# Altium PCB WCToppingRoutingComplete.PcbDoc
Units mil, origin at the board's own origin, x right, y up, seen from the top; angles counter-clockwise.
Board outline 4005 x 4000 mil, 4 copper layers (Top Layer, GND, 5V, Bottom Layer), stack 30.634 mil thick; 56 components, 71 nets, 273 pads, 45 vias.
Unrouted connection lines stored in the file: 67.
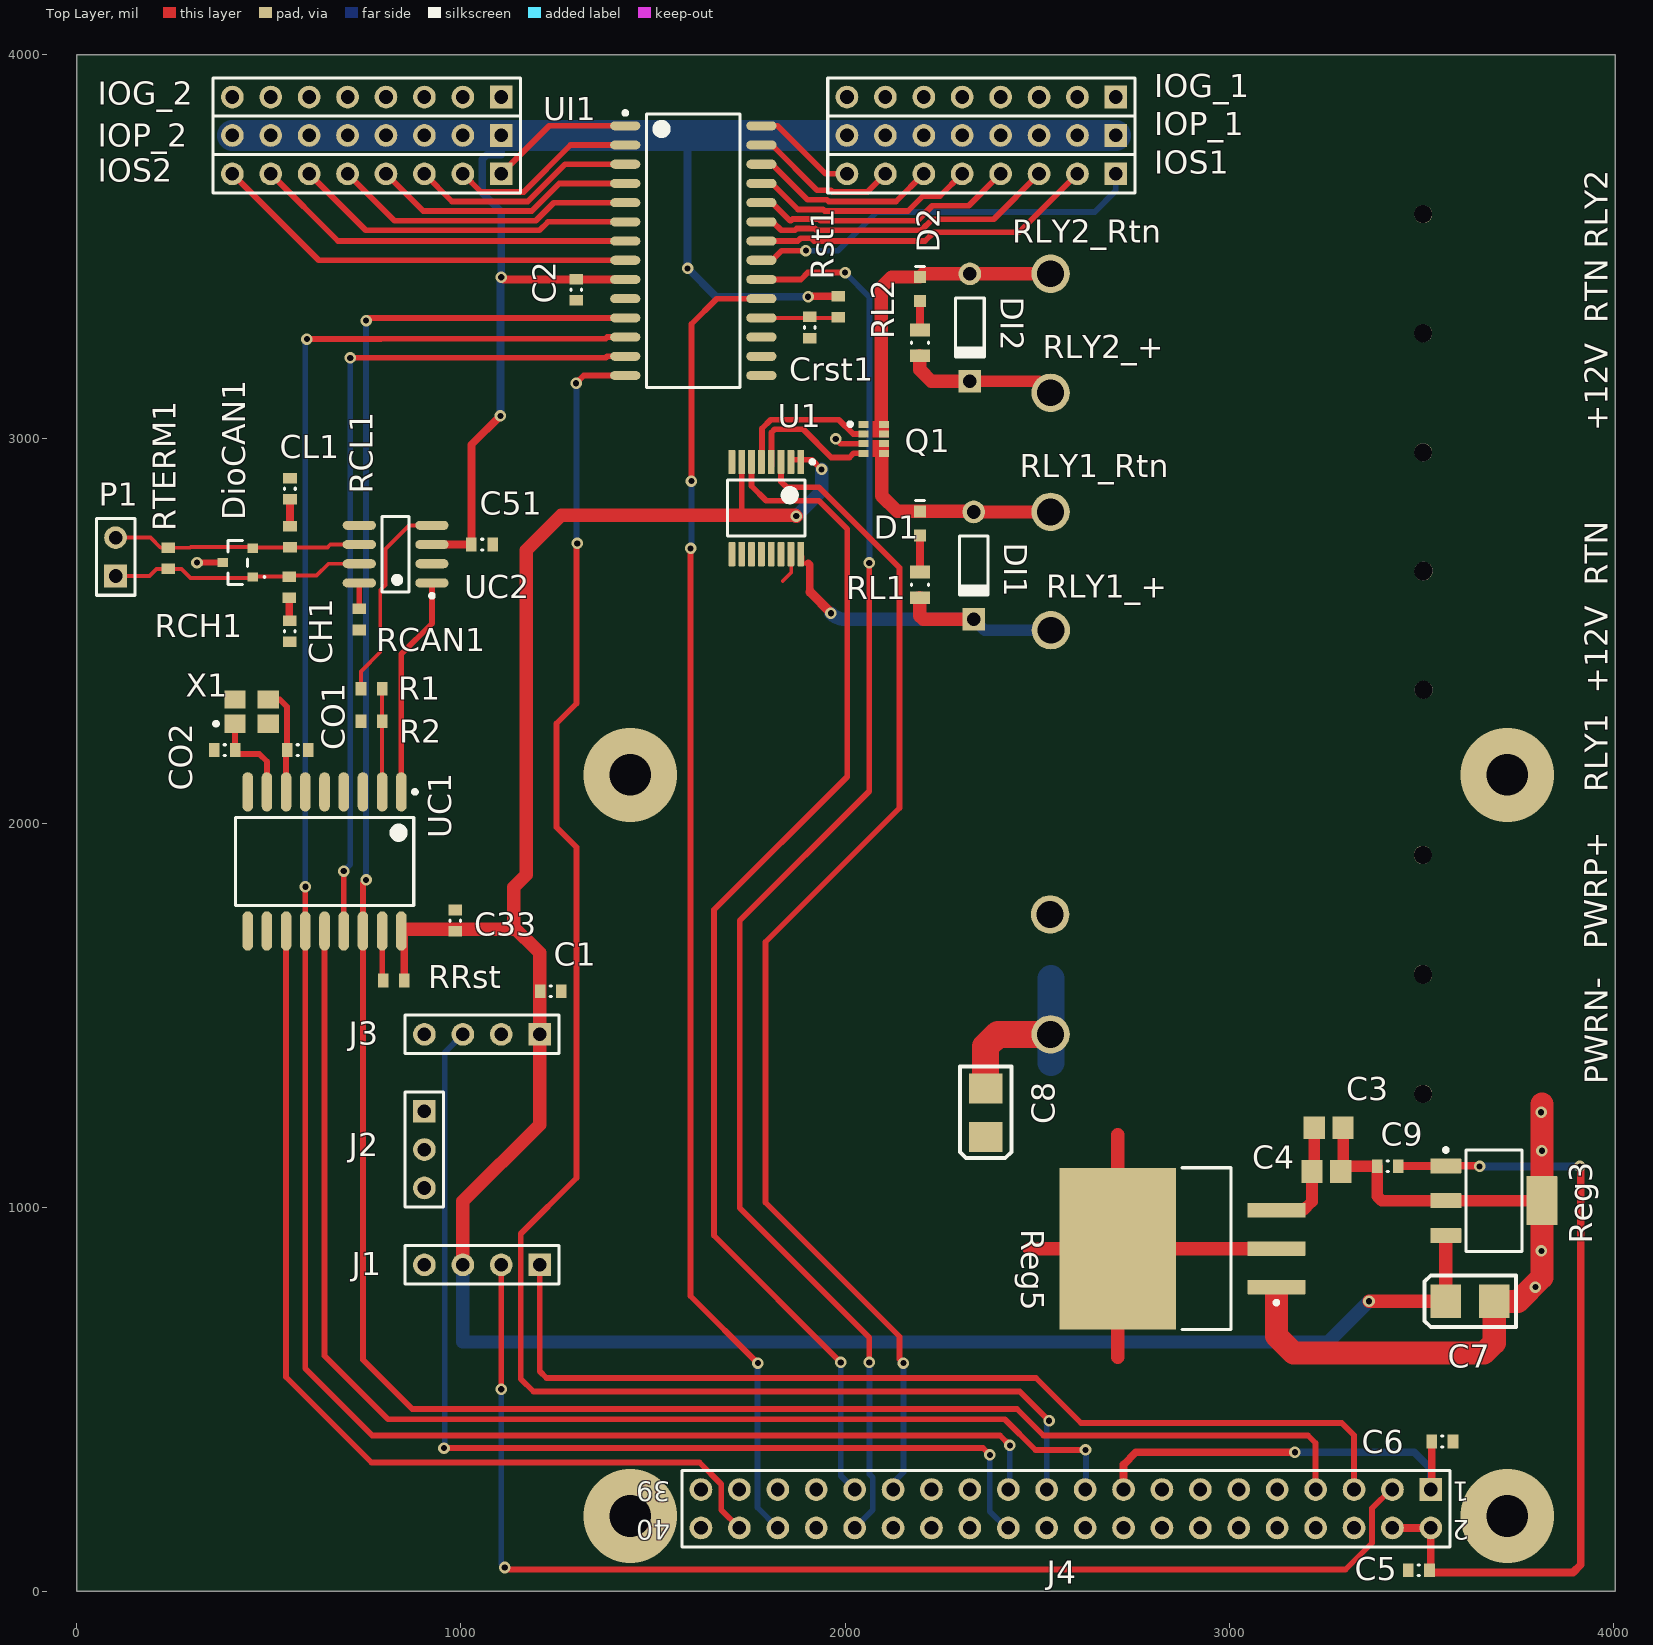
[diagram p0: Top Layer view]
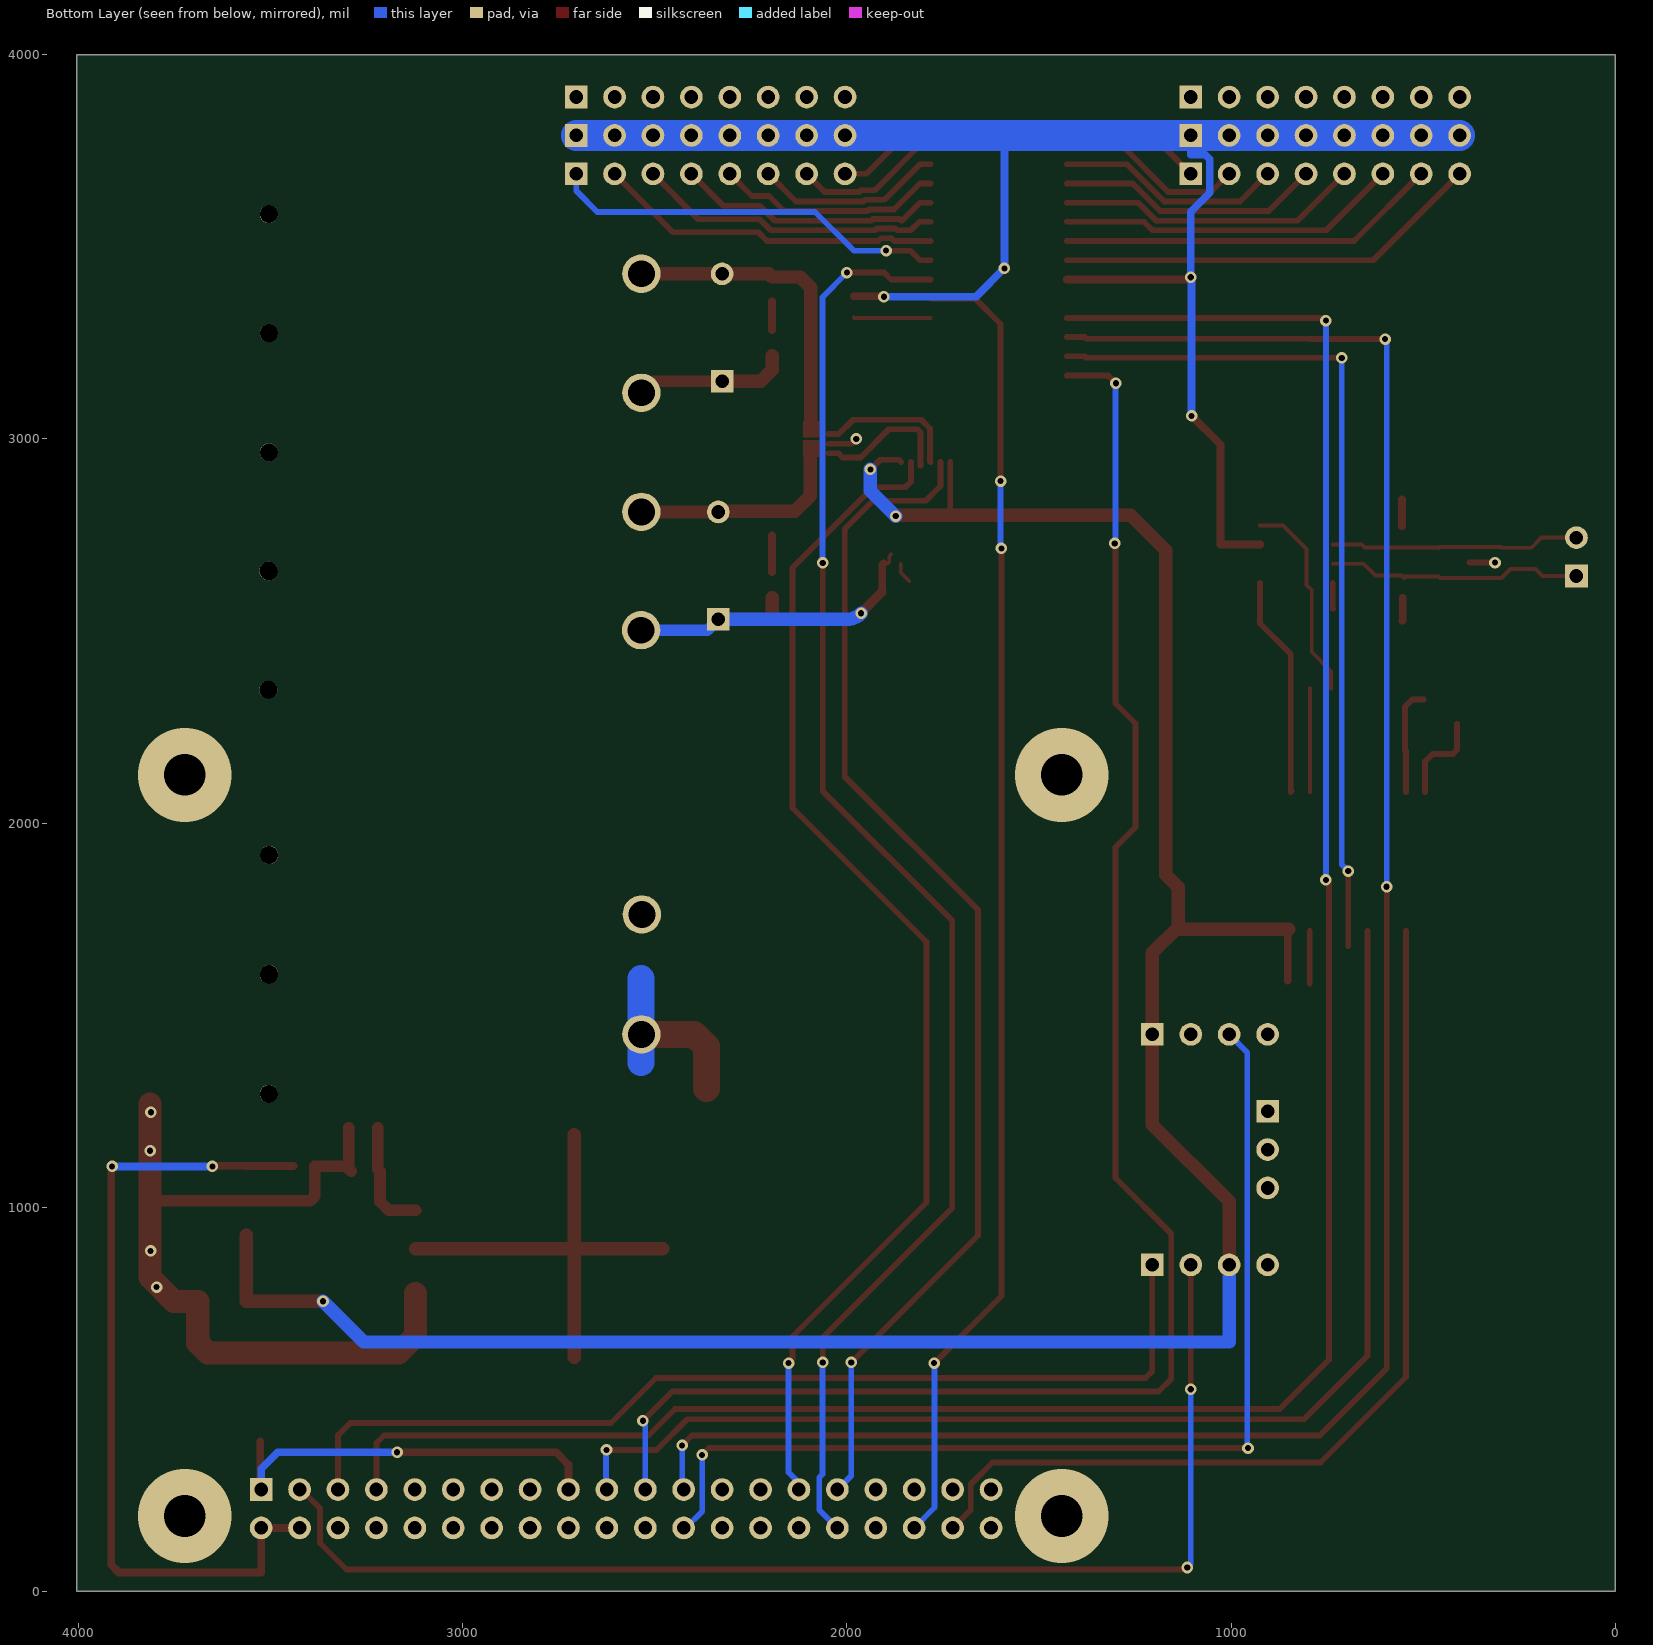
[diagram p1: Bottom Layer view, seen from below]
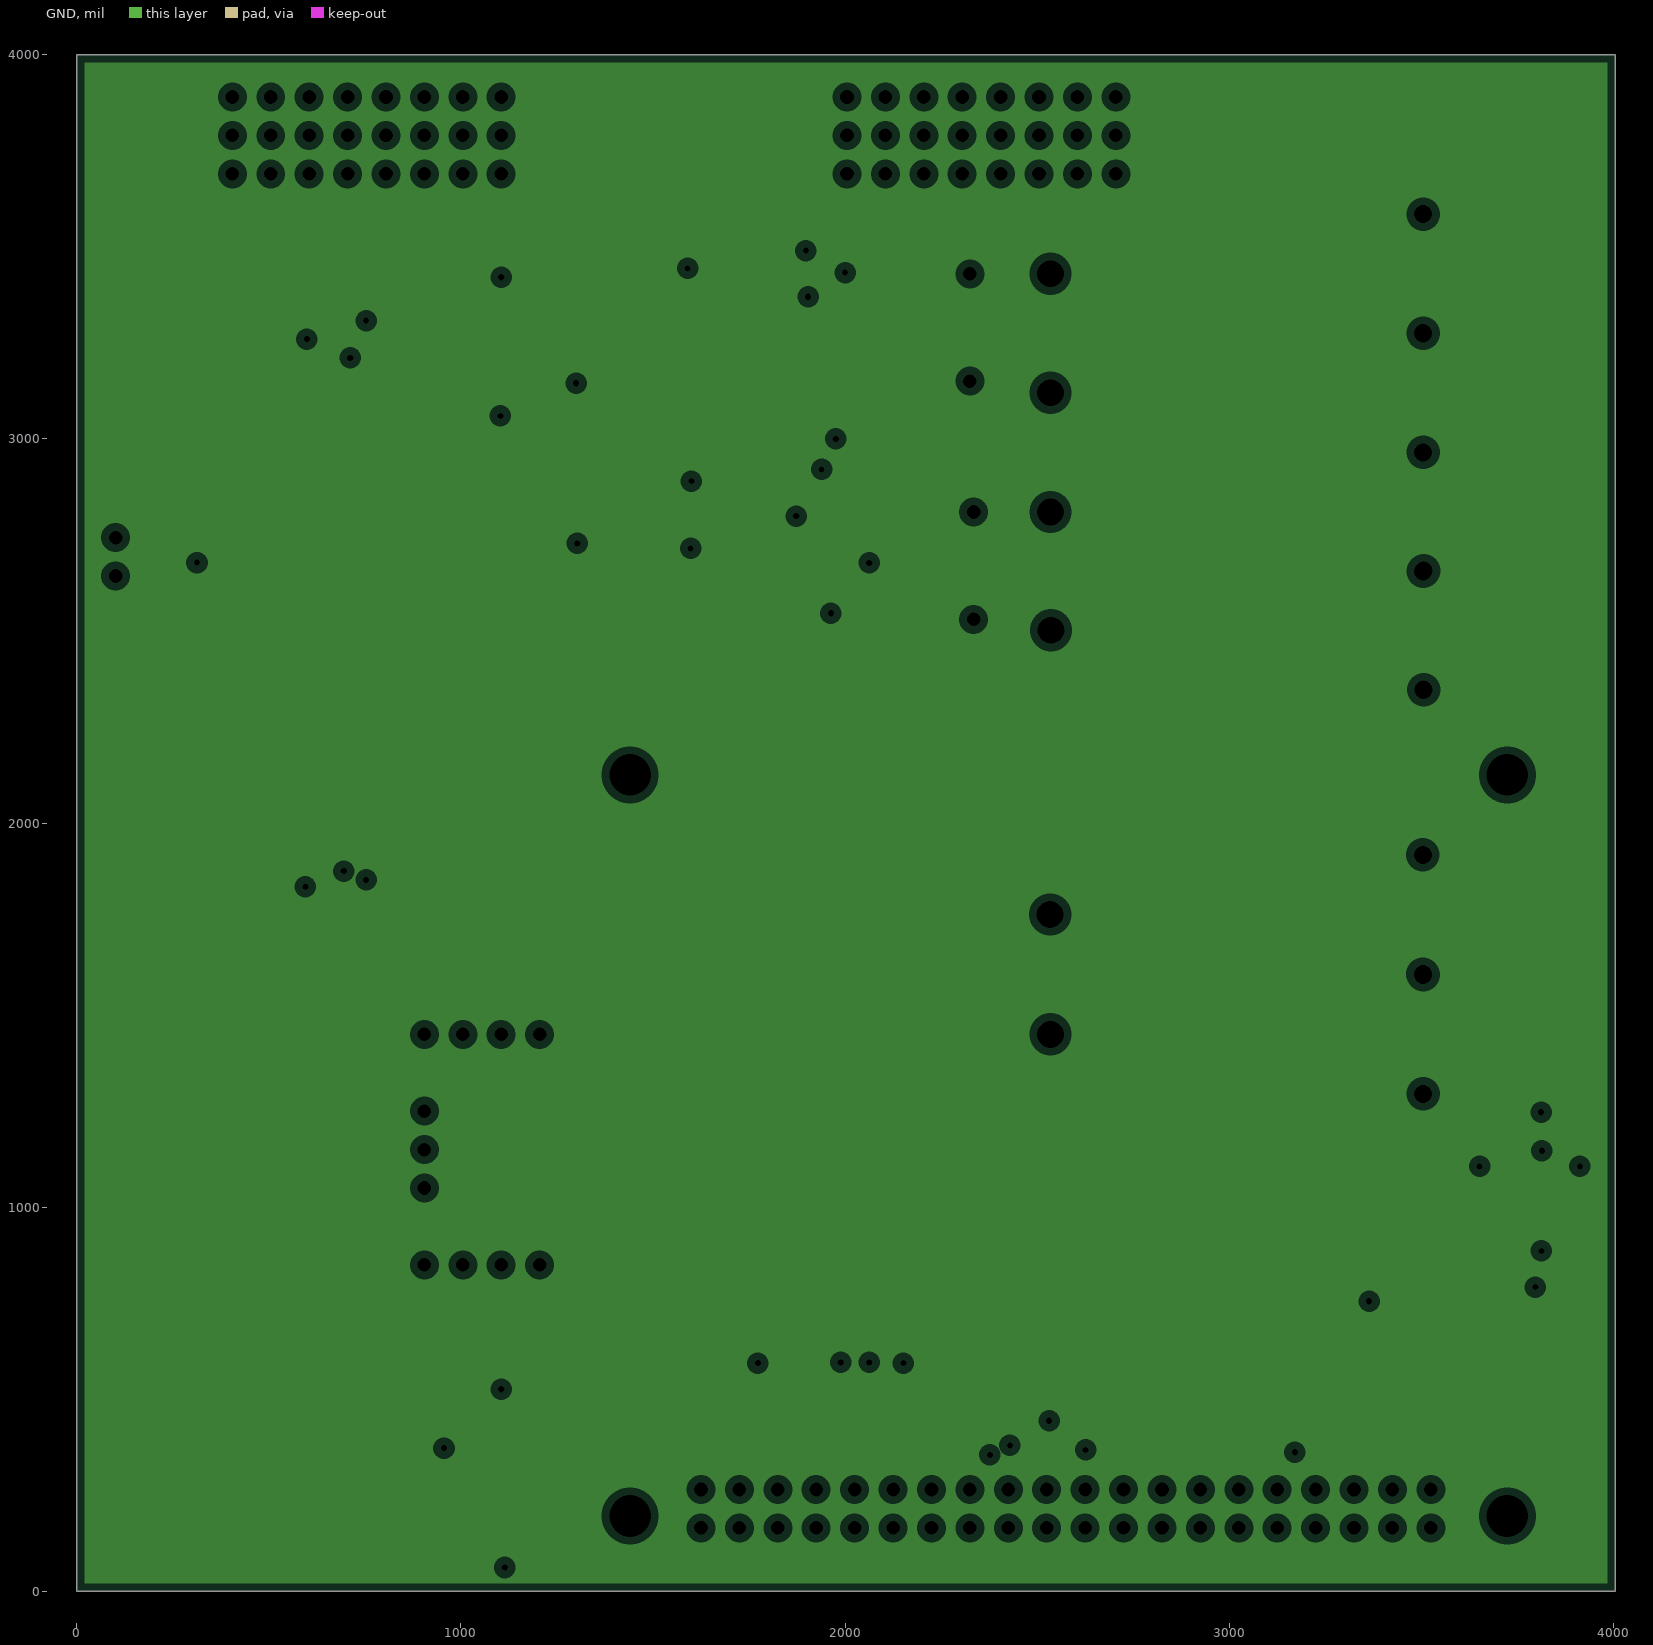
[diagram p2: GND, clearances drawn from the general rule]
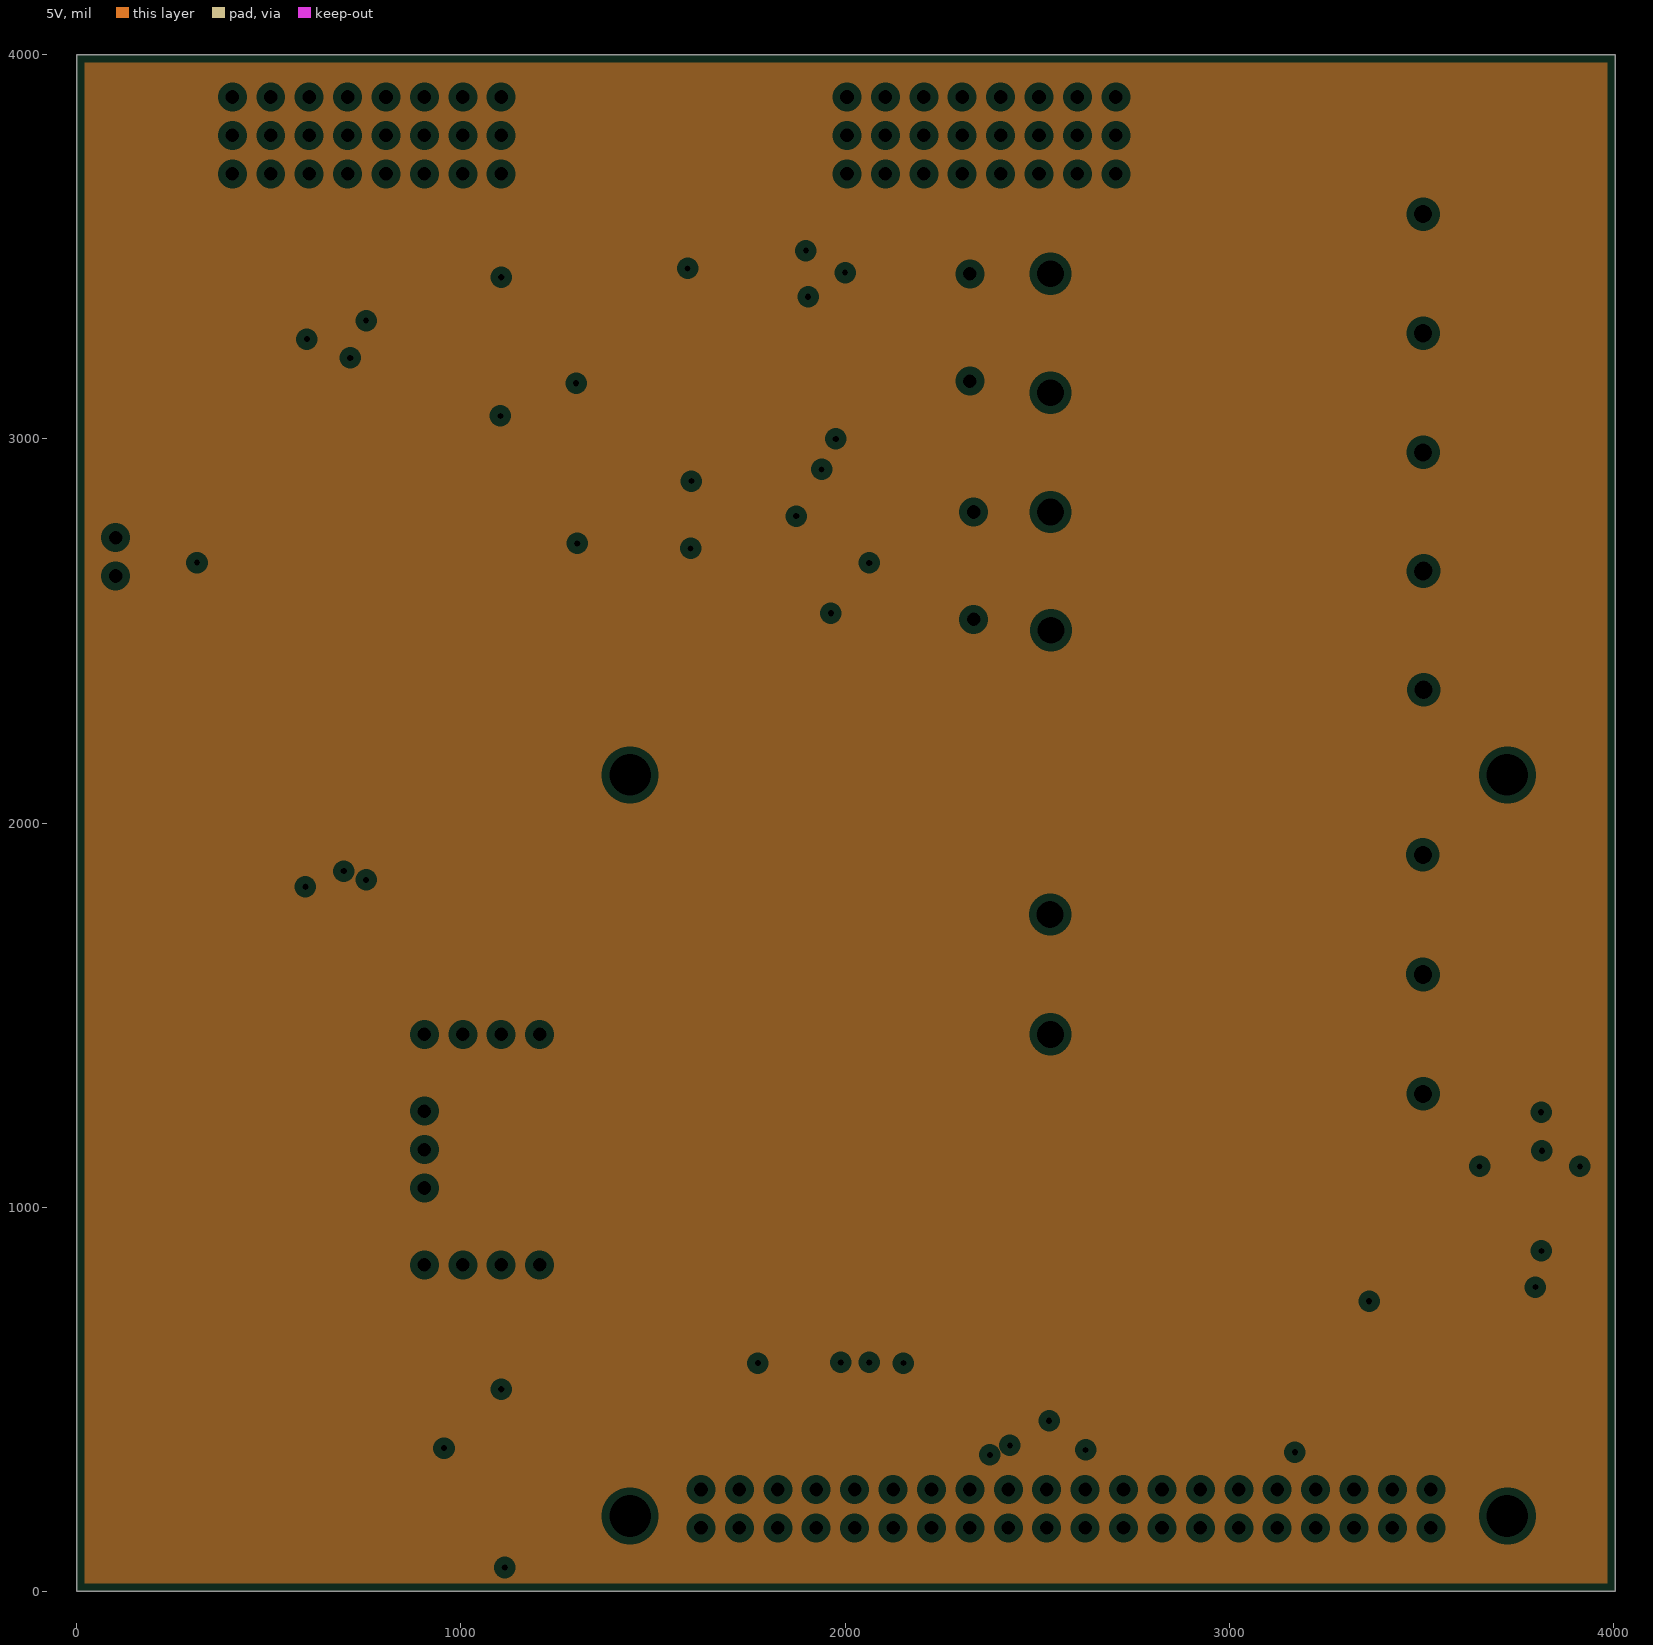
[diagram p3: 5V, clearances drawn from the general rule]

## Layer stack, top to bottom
Top Solder: solder mask 0.4, Solder Resist, Dk 3.5
Top Layer: signal copper 1.4
Dielectric 1: core 10, FR-4, Dk 4.2
GND: plane copper 1.417
Dielectric 3: prepreg 5, Dk 4.2
5V: plane copper 1.417
Dielectric 2: core 10, Dk 4.2
Bottom Layer: signal copper 1.4
Bottom Solder: solder mask 0.4, Solder Resist, Dk 3.5

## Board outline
0,0 4005,0 4005,4000 0,4000

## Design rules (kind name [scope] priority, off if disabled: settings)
BoardOutlineClearance [All] p1: gap=10 ignorepadtopadclearanceinfootprint=FALSE except(0: Arc-SplitContinuation Track-SplitContinuation SMDPad-SplitContinuation THPad-SplitContinuation Via-SplitContinuation Fill-SplitContinuation Poly-SplitContinuation Region-SplitContinuation Text-SplitContinuation)
Clearance "Schematic Clearance Constraint" [InNetClass('CAN')] p1: gap=20 ignorepadtopadclearanceinfootprint=FALSE
Clearance Clearance_1 [(HasFootprint('ONSC-CHIPFET-8-1206A-03_S2_V') AND (IsFill OR IsPad))] p2: gap=2 ignorepadtopadclearanceinfootprint=TRUE
Clearance Clearance_2 [HasFootprint('PW0016A_M') AND (IsFill OR IsPad)] p3: gap=5 ignorepadtopadclearanceinfootprint=TRUE
Clearance 12V_Clearance [InNet('12V') vs Not (InComponent('C3') or InComponent('C4'))] p4: gap=20 ignorepadtopadclearanceinfootprint=FALSE // Need added clearance for 12V tracks
Clearance [All] p5: gap=10 ignorepadtopadclearanceinfootprint=FALSE except(0: Arc-Hole Track-Hole SMDPad-Hole THPad-Hole Via-Hole Fill-Hole Poly-Hole Region-Hole Text-Hole)
ComponentClearance ComponentClearance_1 [HasFootprint('HDR1X8') vs HasFootprint('HDR1X8')] p1: gap=0 collisioncheckmode=3 verticalgap=0 showdistances=FALSE
ComponentClearance Anderson [(ObjectKind = 'Component') And (Footprint = 'Anderson_BLK_RHT_BOT') vs (ObjectKind = 'Component') And (Footprint = 'Anderson_Red_RHT_BOT')] p2: gap=-5 collisioncheckmode=3 verticalgap=10 showdistances=FALSE
ComponentClearance [All] p3: gap=10 collisioncheckmode=3 verticalgap=10 showdistances=FALSE
HoleSize [All] p1: absolutevalues=TRUE maxlimit=110 minlimit=1 maxpercent=80.000 minpercent=20.000
HoleToHoleClearance [(Footprint= 'Anderson_Red_RHT_BOT') or (Footprint = 'Anderson_BLK_RHT_BOT') vs (Footprint= 'Anderson_Red_RHT_BOT') or (Footprint = 'Anderson_BLK_RHT_BOT')] p1: gap=10 allowstackedmicrovias=TRUE
MinimumSolderMaskSliver [All] p1: minsoldermaskwidth=7
PlaneClearance [All] p1: clearance=20
PlaneConnect [All] p1: planeconnectstyle=Relief reliefexpansion=20 reliefentries=4 reliefconductorwidth=10 reliefairgap=10
PolygonConnect [All] p1: connectstyle=Relief reliefconductorwidth=10 reliefentries=4 polygonreliefangle="90 Angle" airgapwidth=10
RoutingVias [All] p1: holewidth=16 width=30 viastyle="Through Hole" minholewidth=12 minwidth=25 maxholewidth=110 maxwidth=250
ShortCircuit AndersonConnector [(ObjectKind = 'Pad') And (Layer = 'MultiLayer') And (AsMils(HoleDiameter) = 47)] p1: allowed=TRUE
ShortCircuit [All] p2: allowed=FALSE
SilkToSolderMaskClearance [IsPad] p1: minsilkscreentomaskgap=5 clearancetoexposedcopper=TRUE
SolderMaskExpansion [All] p1: expansion=4
Width "Schematic Width Constraint_1" [InNetClass('CAN')] p1: maxlimit=30 minlimit=10 preferedwidth=20
Width PowerNets [InNetClass('PowerNets')] p2: maxlimit=100 minlimit=10 preferedwidth=30 // These nets need to handle higher currents
Width [All] p3: maxlimit=20 minlimit=10 preferedwidth=15
22 further rules are at their usual default settings.

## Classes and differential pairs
net class RELAY[1..2]: RELAY1 RELAY2
net class PowerNets: 3V3bd 5V 12V GND NetD1_1 NetD2_1
component class RLY_IO: D1 D2 DI1 DI2 Q1 RL1 RL2 RLY1_Rtn RLY2_+ RLY2_Rtn U1
component class Processor_Interface: C5 C6 J4
component class "Power Supply": C3 C4 C7 C8 C9 PWRN- PWRP+ Reg3 Reg5
component class "Dig IO": C1 C2 Crst1 IOG_1 IOG_2 IOP_1 IOP_2 IOS1 IOS2 J1 J2 J3 Rst1 UI1
component class "CAN Interface": C33 C51 CH1 CL1 CO1 CO2 DioCAN1 P1 R1 R2 RCAN1 RCH1 RCL1 RRst RTERM1 UC1 UC2 X1
net class CAN: CAN_RXD CAN_TXD CANH CANL

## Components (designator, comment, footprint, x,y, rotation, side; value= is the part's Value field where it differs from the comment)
C1 "100nF 50V" 0603C_L 1234,1562 r180 top
C2 "100nF 50V" 0603C_L 1300,3388 r90 top
C3 "10µF" CAPC2013X135X45ML10T25 3259,1207 r180 top
C4 "10µF" CAPC2013X135X45ML10T25 3253,1093 r180 top
C5 "100nF 50V" 0603C_L 3494,55 r0 top
C6 "100nF 50V" 0603C_L 3555,390 r180 top
C7 "33uF" AVX-CAPC3528_V 3627,755 r0 top
C8 "10uF" AVX-CAPC3528_V 2366,1246 r90 top
C9 "100nF 50V" 0603C_L 3413,1107 r0 top
C33 "0.1uF" 0603C_L 985,1746 r270 top
C51 "0.1uF" 0603C_L 1055,2725 r180 top
CH1 "560pF 25V 0603" 0603C_L 554,2499 r270 top
CL1 "560pF 25V 0603" 0603C_L 555,2870 r270 top
CO1 "22pF" 0603C_L 575,2190 r180 top
CO2 "22pF" 0603C_L 385,2190 r180 top
Crst1 "100nF 50V" 0603C_L 1908,3290 r90 top
D1 "LED Red" 0603_A 2195,2780 r270 top
D2 "LED Red" 0603_A 2195,3390 r270 top
DI1 "100V 1A Fast Diode" DO-35 2335,2670 r270 top
DI2 "100V 1A Fast Diode" DO-35 2325,3290 r270 top
DioCAN1 "100V 1A Fast Diode" SOT23 419,2678 r180 top
IOG_1 "Header 8" HDR1X8 2705,3890 r180 top
IOG_2 "Header 8" HDR1X8 1105,3890 r180 top
IOP_1 "Header 8" HDR1X8 2705,3790 r180 top
IOP_2 "Header 8" HDR1X8 1105,3790 r180 top
IOS1 "Header 8" HDR1X8 2705,3690 r180 top
IOS2 "Header 8" HDR1X8 1105,3690 r180 top
J1 "Header 4" HDR1X4 1205,850 r180 top
J2 "Header 3" HDR1X3 905,1250 r270 top
J3 "Header 4" HDR1X4 1205,1450 r180 top
J4 "Header 20X2" HDR2X20 3525,265 r180 top locked
P1 "Header 2" HDR1X2 101,2643 r90 top
PWRN- "BLK_PCB_RHT" Anderson_BLK_RHT_BOT 2535,1450 r180 top
PWRP+ "RED_PCB_RHT" Anderson_Red_RHT_BOT 2534,1762 r180 top
Q1 "NTHD4508NT1" ONSC-CHIPFET-8-1206A-03_S2_V 2075,3000 r0 top
R1 "10K 0603" 0603_L 767.44,2350 r0 top
R2 "22K" 0603_L 767.44,2265 r0 top
RCAN1 "4.7K" 0603_L 735,2530 r90 top
RCH1 "100" 0603_L 553,2614 r90 top
RCL1 "100" 0603_L 555,2745 r270 top
Reg3 "3.3V" DCY0004A_M 3689,1017 r0 top
Reg5 "LM1084IS-5.0/NOPB" KTT0003B_L 2879,892 r180 top
RL1 "1K 0805" 0805_L 2195,2620 r270 top
RL2 "1K 0805" 0805_L 2195,3250 r270 top
RLY1_+ "Anderson-1Pin RED_PCB_RHT" Anderson_Red_RHT_BOT 2536,2502 r180 top
RLY1_Rtn "Anderson-1Pin BLK_PCB_RHT" Anderson_BLK_RHT_BOT 2535,2810 r180 top
RLY2_+ "Anderson-1Pin RED_PCB_RHT" Anderson_Red_RHT_BOT 2535,3120 r180 top
RLY2_Rtn "Anderson-1Pin BLK_PCB_RHT" Anderson_BLK_RHT_BOT 2535,3430 r180 top
RRst "10K 0603" 0603_L 825,1590 r0 top
Rst1 "10K 0603" 0603_L 1982,3344 r90 top
RTERM1 "22K" 0603_L 238,2689 r270 top
U1 "CD40109BPW" PW0016A_M 1795,2820 r270 top
UC1 "MCP2515-E/SO" SOIC-SO18_M 645,1900 r270 top
UC2 "MCP2551-E/SN" SOIC-SN8_N 830,2700 r180 top
UI1 "MCP23S17T-E/SO" SOIC-SO28_L 1605,3490 r0 top
X1 "21C00047-16.000MHz" ITTI-21C00047-16.000MHz-4_V 455,2290 r0 top

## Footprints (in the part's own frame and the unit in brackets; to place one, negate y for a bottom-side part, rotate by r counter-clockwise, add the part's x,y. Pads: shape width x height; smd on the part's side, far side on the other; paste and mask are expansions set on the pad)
0603_A [mm] "Chip LED, 2-Leads, Body 1.6x0.8mm, IPC Medium Density"
  rect 0.8x0.8 smd: 1(-0.8,0) 2(0.8,0)
  silkscreen extent -1.5,-0.3 -1.5,0.3, body extent -0.8,-0.4 0.8,0.4, height 0.7
0603_L [mm]
  rect 0.7x0.9 smd: 1(-0.7,0) 2(0.7,0)
  body extent -0.85,-0.47 0.85,0.47, height 0.6
0603C_L [mm]
  rect 0.7x0.9 smd: 1(-0.7,0) 2(0.7,0)
  silkscreen extent -0.05,-0.35 0.05,0.35, body extent -0.87,-0.47 0.88,0.48, height 1
0805_L [mm]
  rect 0.85x1.3 smd: 1(-0.85,0) 2(0.85,0)
  silkscreen extent -0.05,-0.55 0.05,0.55, body extent -1.1,-0.67 1.1,0.68, height 0.7
Anderson_BLK_RHT_BOT [mil]
  round 100 hole 70: 1(0,0)
  round 47 hole 47 unplated: MH(-970,-155) MH(-970,155)
  body extent -1360,-155 25,155, height 310
Anderson_Red_RHT_BOT [mil]
  round 100 hole 70: 1(0,0)
  round 47 hole 47 unplated: MH(-970,-155) MH(-970,155)
  body extent -1360,-155 25,155, height 310
AVX-CAPC3528_V [mm] "SMT Capacitor, 2 Leads, Body 3.5x2.8mm"
  rect 2x2.2 smd: 1(-1.6,0) 2(1.6,0)
  silkscreen extent -3,-1.7 3.05,1.7, body extent -1.79,-1.54 1.8,1.54, height 1.9
CAPC2013X135X45ML10T25 [mm] "Chip Capacitor, 2-Leads, Body 2.00x1.25mm, IPC Low Density"
  rect 1.4x1.5 smd: 1(-0.95,0) 2(0.95,0)
  body extent -1.05,-0.67 1.05,0.67, height 1.35
DCY0004A_M [mm] "SOT223, 4-Leads, Body 6.7x3.7mm, Pitch 2.3mm, IPC Low Density"
  rrect10% 2.05x1 smd: 1(-3.175,2.3) 2(-3.175,0) 3(-3.175,-2.3)
  rrect5% 2.05x3.25 smd: 4(3.175,0)
  silkscreen extent -3.3,-3.35 1.85,3.47, body extent -3.5,-3.25 3.5,3.25, height 1.62
DO-35 [mm] "Diode, Axial; Body 3.8 x 1.9 mm (LxDia. max), Lead Dia. 0.53 mm (max)"
  round 1.5 hole 0.9: 1(-3.55,0)
  rect 1.5x1.5 hole 0.9: 2(3.55,0)
  silkscreen extent -1.95,-0.95 2.05,0.95
HDR1X2 [mm] "Connector; Header; 2 Position"
  rect 1.5x1.5 hole 0.9: 1(0,0)
  round 1.5 hole 0.9: 2(2.54,0)
  silkscreen extent -1.27,-1.27 3.81,1.27
HDR1X3 [mm] "Connector; Header; 3 Position"
  rect 1.5x1.5 hole 0.9: 1(0,0)
  round 1.5 hole 0.9: 2(2.54,0) 3(5.08,0)
  silkscreen extent -1.27,-1.27 6.35,1.27
HDR1X4 [mm] "Connector; Header; 4 Position"
  rect 1.5x1.5 hole 0.9: 1(0,0)
  round 1.5 hole 0.9: 2(2.54,0) 3(5.08,0) 4(7.62,0)
  silkscreen extent -1.27,-1.27 8.89,1.27
HDR1X8 [mm] "Connector; Header; 8 Position"
  rect 1.5x1.5 hole 0.9: 1(0,0)
  round 1.5 hole 0.9: 2(2.54,0) 3(5.08,0) 4(7.62,0) 5(10.16,0) 6(12.7,0) 7(15.24,0) 8(17.78,0)
  silkscreen extent -1.27,-1.27 19.05,1.27
HDR2X20 [mm] "Connector; Header; 20x2 Position"
  rect 1.5x1.5 hole 0.9: 1(0,0)
  round 1.5 hole 0.9: 2(0,2.54) 3(2.54,0) 4(2.54,2.54) 5(5.08,0) 6(5.08,2.54) 7(7.62,0) 8(7.62,2.54) 9(10.16,0) 10(10.16,2.54) 11(12.7,0) 12(12.7,2.54) 13(15.24,0) 14(15.24,2.54) 15(17.78,0) 16(17.78,2.54) 17(20.32,0) 18(20.32,2.54) 19(22.86,0) 20(22.86,2.54) 21(25.4,0) 22(25.4,2.54) 23(27.94,0) 24(27.94,2.54) 25(30.48,0) 26(30.48,2.54) 27(33.02,0) 28(33.02,2.54) 29(35.56,0) 30(35.56,2.54) 31(38.1,0) 32(38.1,2.54) 33(40.64,0) 34(40.64,2.54) 35(43.18,0) 36(43.18,2.54) 37(45.72,0) 38(45.72,2.54) 39(48.26,0) 40(48.26,2.54)
  silkscreen extent -1.27,-1.27 49.53,3.81
ITTI-21C00047-16.000MHz-4_V [mm] "Hand Drawn, 4-Leads, Body 3.2x2.5 mm"
  rect 1.4x1.2 smd: 1(-1.1,-0.8) 2(1.1,-0.8) 3(1.1,0.8) 4(-1.1,0.8)
  silkscreen extent -2.47,-0.92 -2.23,-0.68, body extent -1.6,-1.25 1.6,1.25, height 0.9
KTT0003B_L [mm] "DPAK, 3-Leads, Body 10.65x9.65mm, Pitch 2.54mm, IPC High Density"
  rrect11% 3.85x0.95 smd: 1(-6.2,2.54) 2(-6.2,0) 3(-6.2,-2.54)
  rrect1% 7.7x10.7 smd: 4(4.3,0)
  silkscreen extent -6.33,-5.35 0.05,5.35, body extent -7.8,-5.08 6.5,5.08, height 4.72
ONSC-CHIPFET-8-1206A-03_S2_V [mil] "SON, 8-Leads, Body 3.025x1.625mm, Pitch 0.635mm"
  rect 25.98x17.99 smd: 1(-27.01,37.5) 2(-27.01,12.5) 3(-27.01,-12.5) 4(-27.01,-37.5) 5(27.01,-37.5) 6(27.01,-12.5) 7(27.01,12.5) 8(27.01,37.5)
  Top Layer region: -4.02,-46.5 40,-46.5 40,-3.5 -4.02,-3.5
  Top Layer region: -4.02,3.5 40,3.5 40,46.5 -4.02,46.5
  silkscreen extent -67,33 -57,43, body extent -32,-60 32,60, height 43
PW0016A_M [mm] "SOP, 16-Leads, Body 5.1x4.5mm, Pitch 0.65mm, IPC Low Density"
  rrect22% 1.6x0.45 smd: 1(-3.05,2.275) 2(-3.05,1.625) 3(-3.05,0.975) 4(-3.05,0.325) 5(-3.05,-0.325) 6(-3.05,-0.975) 7(-3.05,-1.625) 8(-3.05,-2.275) 9(3.05,-2.275) 10(3.05,-1.625) 11(3.05,-0.975) 12(3.05,-0.325) 13(3.05,0.325) 14(3.05,0.975) 15(3.05,1.625) 16(3.05,2.275)
  silkscreen extent -3.17,-2.55 1.85,3.17, body extent -3.21,-2.5 3.21,2.5, height 1
SOIC-SN8_N [mm] "SOIC, 8-Leads, Body 4.9x3.9mm, Pitch 1.27mm, IPC Medium Density"
  oval 2.2x0.6 smd: 1(-2.4,1.905) 2(-2.4,0.635) 3(-2.4,-0.635) 4(-2.4,-1.905) 5(2.4,-1.905) 6(2.4,-0.635) 7(2.4,0.635) 8(2.4,1.905)
  silkscreen extent -2.53,-2.5 0.9,2.88, body extent -2,-2.5 2,2.5, height 1.75
SOIC-SO18_M [mm] "SOIC, 18-Leads, Body 11.6x7.5mm, Pitch 1.27mm, IPC Low Density"
  oval 2.6x0.7 smd: 1(-4.6,5.08) 2(-4.6,3.81) 3(-4.6,2.54) 4(-4.6,1.27) 5(-4.6,0) 6(-4.6,-1.27) 7(-4.6,-2.54) 8(-4.6,-3.81) 9(-4.6,-5.08) 10(4.6,-5.08) 11(4.6,-3.81) 12(4.6,-2.54) 13(4.6,-1.27) 14(4.6,0) 15(4.6,1.27) 16(4.6,2.54) 17(4.6,3.81) 18(4.6,5.08)
  silkscreen extent -4.72,-5.9 2.9,6.11, body extent -3.8,-5.87 3.8,5.87, height 2.65
SOIC-SO28_L [mm] "SOIC, 28-Leads, Body 17.9x7.5mm, Pitch 1.27mm, IPC High Density"
  oval 2x0.6 smd: 1(-4.5,8.255) 2(-4.5,6.985) 3(-4.5,5.715) 4(-4.5,4.445) 5(-4.5,3.175) 6(-4.5,1.905) 7(-4.5,0.635) 8(-4.5,-0.635) 9(-4.5,-1.905) 10(-4.5,-3.175) 11(-4.5,-4.445) 12(-4.5,-5.715) 13(-4.5,-6.985) 14(-4.5,-8.255) 15(4.5,-8.255) 16(4.5,-6.985) 17(4.5,-5.715) 18(4.5,-4.445) 19(4.5,-3.175) 20(4.5,-1.905) 21(4.5,-0.635) 22(4.5,0.635) 23(4.5,1.905) 24(4.5,3.175) 25(4.5,4.445) 26(4.5,5.715) 27(4.5,6.985) 28(4.5,8.255)
  silkscreen extent -4.62,-9.05 3.1,9.23, body extent -3.8,-9.05 3.8,9.05, height 2.65
SOT23 [mm]
  rect 0.7x0.6 smd paste-0.05: 1(-1,0.95) 2(-1,-0.95) 3(1,0)
  silkscreen extent -1.79,-1.45 0.65,1.45, body extent -1.3,-1.5 1.3,1.5, height 1.1

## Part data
C1 C2 C5 C6 C9 Crst1: library part Cap100nF_50V_0603, Capacitance=0.10µF, Manufacturer=Yageo, Manufacturer Part Number=CC0603ZRY5V9BB104, Operating Temperature="-30°C ~ 85°C", Package / Case="0603 (1608 Metric)", Ratings=-, Supplier Part Number 1=311-1343-1-ND, Temperature Coefficient="Y5V (F)", Tolerance="-20%, +80%", Voltage - Rated=50V
C3 C4: library part CMP-2007-03541-1, Manufacturer=Murata, Manufacturer Part Number=GRM21BR61E106KA73L, Operating Temperature="-55°C ~ 85°C", Package / Case="0805 (2012 Metric)", Ratings=-, Standard Package=1, Supplier Part Number 1=490-5523-1-ND, Temperature Coefficient=X5R, Tolerance=±10%, Voltage - Rated=25V
C7: library part CMP-0279-00001-1, "Capacitor, Tantalum, 10uF 10% 20V MCCT-B (3528)", ESR (Equivalent Series Resistance)=-, Manufacturer="Kyocera / AVX", Manufacturer Part Number=TAJB336K006RNJ, Manufacturer Size Code=B, Operating Temperature="-55°C ~ 125°C", Package / Case="1210 (3528 Metric)", PCN Part Number="TAJ Series Suffix 08/Dec/2008", Standard Package=1, Supplier Part Number 1=478-8891-6-ND, Tolerance=±10%, Voltage - Rated=6.3V
C8: library part CMP-0279-00001-1, "Capacitor, Tantalum, 10uF 10% 20V MCCT-B (3528)", Case Code=B, Case Style=Molded, Manufacturer=AVX, Manufacturer Part Number=TAJB106K020RNJ, Operating Temp Range="-55C to 125C", Package / Case=3528-21, PartNumber=TAJB106K020R, Rated Voltage=20V, Supplier Part Number 1=478-1674-6-ND, Tolerance=10%, Voltage=20VDC
C33 C51: library part Cap10uF_25V_0603
CH1 CL1: library part Cap560pF_25V_0603, Capacitance=10µF, Manufacturer="Taiyo Yuden", Manufacturer Part Number=TMK316F106ZL-T, Operating Temperature="-30°C ~ 85°C", Package / Case="1206 (3216 Metric)", Ratings=-, Standard Package=1, Supplier Part Number 1=587-1353-1-ND, Temperature Coefficient="Y5V (F)", Tolerance="-20%, +80%", Voltage - Rated=25V
CO1: library part Cap22pF_50V_0603, Capacitance=22, Case/Package=0603, Case Code (Metric)=1608, Manufacturer=Murata, Manufacturer Part Number=GRM1885C1H220JA01D, Max Operating Temperature=125, Min Operating Temperature=-55, Package Quantity=1, Supplier Part Number 1=490-1411-1-ND, Tolerance=5, Type (Capacitors)=C0G, Voltage Rating=50
CO2: library part Cap100nF_50V_0603, Capacitance=22, Case/Package=0603, Case Code (Metric)=1608, Manufacturer=Murata, Manufacturer Part Number=GRM1885C1H220JA01D, Max Operating Temperature=125, Min Operating Temperature=-55, Package Quantity=1, Supplier Part Number 1=490-1411-1-ND, Tolerance=5, Type (Capacitors)=C0G, Voltage Rating=50
D1 D2: library part LED_Red0603, "SMD mono-color Chip LED, WL-SMCW, Red", Color=Red, Current - Test=20mA, Lens Color=Colorless, Manufacturer="Wurth Electronics Inc", Manufacturer Part Number=150060RS75000, Millicandela Rating=250mcd, Package / Case="0603 (1608 Metric)", Supplier Device Package=0603, Supplier Part Number 1=732-4978-1-ND, Voltage - Forward (Vf) (Typ)=2V
DI1 DI2: library part "Diode 1N4148", "High Conductance Fast Diode", Diode Case Style=DO-204AL, Forward Current If(AV)=1A, Forward Surge Current Ifsm Max=35A, Forward Voltage VF Max=1.25V, Manufacturer="ON Semiconductor", Manufacturer Part Number=MUR110RLG, Operating Temperature Max=175°C, Repetitive Reverse Voltage Vrrm Max=100V, Supplier Part Number 1=MUR110RLGOSCT-ND
DioCAN1: library part PESD1CAN, "High Conductance Fast Diode", Diode Case Style=DO-204AL, Forward Current If(AV)=1A, Forward Surge Current Ifsm Max=35A, Forward Voltage VF Max=1.25V, Manufacturer="ON Semiconductor", Manufacturer Part Number=MUR110RLG, Operating Temperature Max=175°C, Repetitive Reverse Voltage Vrrm Max=100V, Supplier Part Number 1=MUR110RLGOSCT-ND
IOG_1 IOG_2 IOP_1 IOP_2 IOS1 IOS2: "Header, 8-Pin"
J1 J3: "Header, 4-Pin"
J2: "Header, 3-Pin"
J4: "Header, 20-Pin, Dual row"
P1: "Header, 2-Pin"
PWRN-: library part "Anderson-1Pin BLK_PCB_RHT", "1 pin Anderson", Current Rating="25 A", Manufacturer="Anderson Power Products (APP)", Manufacturer Part Number="1377G1, 1377G2, 1327-BK,137G6-BK", Supplier Part Number 1=879-1377G1, Voltage Rating="600 V"
PWRP+: library part "Anderson-1Pin RED_PCB_RHT", "1 pin Anderson", Current Rating="25 A", Manufacturer="Anderson Power Products (APP)", Manufacturer Part Number="1377G1, 1377G2, 1327-BK,137G6-BK", Supplier Part Number 1=879-1377G1, Voltage Rating="600 V"
Q1: "Power MOSFET, 20 V, 4.1 A, Dual N-Channel, 8-Pin CHIPFET, Tape and Reel", Current - Continuous Drain (Id) @ 25°C=3A, Drain to Source Voltage (Vdss)=20V, Input Capacitance (Ciss) @ Vds="180pF @ 10V", Manufacturer="On Semiconductor", Manufacturer Part Number=NTHD4508NT1G, Operating Temperature="-55°C ~ 150°C (TJ)", Package / Case="8-SMD, Flat Lead", Package Type=ChipFET-8, Power - Max=1.13W, Supplier Device Package=ChipFET™, Supplier Part Number 1=NTHD4508NT1GOSCT-ND
R1: library part Res4K99_0603, Manufacturer=Yageo, Manufacturer Part Number=RT0603DRD074K99L, Operating Temperature="-55°C ~ 155°C", Package / Case="0603 (1608 Metric)", Power (Watts)="0.1W, 1/10W", Resistance (Ohms)=10K, Supplier Device Package=0603, Supplier Part Number 1=311-10KDCT-ND, Temperature Coefficient=±25ppm/°C, Tolerance=±0.5%
R2 RTERM1: library part Res_0603, Case Code - in=0603, Case Code - mm=1608, Manufacturer=Yageo, Manufacturer Part Number=RT0603DRD0722KL, Operating Temperature Range="- 55 C to + 125 C", Package / Case="0603 (1608 metric)", Power Rating="100 mW", Resistance="22 kOhms", Supplier Part Number 1=311-22KDDKR-ND, Temperature Coefficient="25 PPM / C", Tolerance="0.5 %", Voltage Rating="75 V"
RCAN1: library part Res4K99_0603, Manufacturer=Yageo, Manufacturer Part Number=RT0603DRD074K99L, Operating Temperature="-55°C ~ 155°C", Package / Case="0603 (1608 Metric)", Power (Watts)="0.1W, 1/10W", Resistance (Ohms)=4.99k, Supplier Device Package=0603, Supplier Part Number 1=311-4.99KDCT-ND, Temperature Coefficient=±25ppm/°C, Tolerance=±0.5%
RCH1 RCL1: library part Res330_0603, Manufacturer=Yageo, Manufacturer Part Number=RC0603JR-07330RL, Operating Temperature="-55°C ~ 155°C", Package / Case="0603 (1608 Metric)", Power (Watts)="0.1W, 1/10W", Resistance (Ohms)=330, Supplier Device Package=0603, Supplier Part Number 1=311-330GRCT-ND, Temperature Coefficient=±100ppm/°C, Tolerance=±5%
Reg3: library part CMP-0062-01788-3, "1A Low Dropout Regulator for 5V to 3.3V Conversion, 4-pin SOT-223, Pb-Free", Dropout Voltage@Current (Typ)=0.5@1A/0.11@100mA, Input Voltage=7.5V, Input Voltage (Min)=4.5V, Manufacturer="Texas Instruments", Manufacturer Part Number=LM3940IMP-3.3/NOPB, Operating Temperature Classification=Automotive, Operating Temp Range="-40C to 125C", Output Current=1A, PackageTopMarking=XYTT*L52B, Package Type=SOT-223, PowerWise=N, Quiescent Current (Max)=15mA, Supplier Part Number 1=LM3940IMP-3.3/NOPBDKR-ND, Voltage Regulator Type=LDO
Reg5: library part CMP-0062-00575-4, "5A Low Dropout Positive Regulators, 3-pin TO-263, Pb-Free", Manufacturer="Texas Instruments", PackageTopMarking=NSUZXYTTE#*LM1084*IS-5.0, PowerWise=N
RL1 RL2: library part Res1K_0805, Manufacturer="Panasonic Electronic Components", Manufacturer Part Number=ERJ-6GEYJ102V, Operating Temperature="-55°C ~ 155°C", Package / Case="0805 (2012 Metric)", Power (Watts)="0.125W, 1/8W", Resistance (Ohms)=1k, Supplier Device Package=0805, Supplier Part Number 1=P1.0KACT-ND, Temperature Coefficient=±200ppm/°C, Tolerance=±5%
RLY1_+ RLY1_Rtn RLY2_+ RLY2_Rtn: "1 pin Anderson", Current Rating="25 A", Manufacturer="Anderson Power Products (APP)", Manufacturer Part Number="1377G1, 1377G2, 1327-BK,137G6-BK", Supplier Part Number 1=879-1377G2, Voltage Rating="600 V"
RRst Rst1: library part Res10K_0603, Manufacturer="Panasonic Electronic Components", Manufacturer Part Number=ERJ-3GEYJ102V, Operating Temperature="-55°C ~ 155°C", Package / Case="0603 (1608 Metric)", Power (Watts)="0.1W, 1/10W", Resistance (Ohms)=1k, Supplier Device Package=0603, Supplier Part Number 1=P10KGCT-ND, Temperature Coefficient=±200ppm/°C, Tolerance=±5%
U1: library part CMP-1527-00010-2, "CMOS Quad Low-to-High Voltage Level Shifter, 3 to 18 V, -55 to 125 degC, 16-Pin TSSOP (PW16), RoHS, Tube", Manufacturer="Texas Instruments", Manufacturer Part Number=CD40109BPWR, Operating Temperature="-55°C ~ 125°C", Package / Case="16-TSSOP (0.173\", 4.40mm Width)", Package Reference=PW0016A, Standard Package=1, Supplier Device Package=16-TSSOP, Supplier Part Number 1=296-12163-6-ND, Temperature Range="-55 to 125 degC", Voltage - Supply="3 V ~ 18 V"
UC1: library part CMP-0186-00035-2, "Stand-Alone CAN Controller With SPI Interface, 18-Pin SOIC, Extended Temperature"
UC2: library part CMP-0186-00038-2, "High-Speed CAN Transceiver, 8-Pin SOIC, Extended Temperature"
UI1: library part CMP-0186-00131-2, "16-Bit I/O Expander with Serial Interface, 28-Pin SOIC, Extended Temperature, Tape and Reel"
X1: library part CMP-0464-00001-2, "Crystal, 16 MHz, -30 to 85 degC, 3.2 x 2.5 x 0.9 mm SMD", Frequency Tolerance="+/-20 ppm", Load Capacitance="10 pF", Manufacturer=ITTI, Nominal Frequency="16 MHz", Operating Temperature="-30 to 85 degC"

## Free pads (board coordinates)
  round 0 on Mech16 paste+0 mask+0: 1(1880,3427)

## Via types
v1: diameter 30, hole 16, Top Layer to Bottom Layer, 41 vias
v2: diameter 244.09, hole 108.27, Top Layer to Bottom Layer, 4 vias

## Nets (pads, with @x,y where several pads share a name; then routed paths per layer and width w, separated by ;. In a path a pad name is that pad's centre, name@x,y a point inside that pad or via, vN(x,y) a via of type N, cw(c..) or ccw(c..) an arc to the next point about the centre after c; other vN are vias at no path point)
3V3: C6.2 J4.1 J4.17 | length 1076.1
  Top Layer w20: J4.17 2725,330 2757,362 v1(3171,362) ; J4.1 3527.44,267.44 C6.2
  Bottom Layer w20: v1(3171,362) 3482,362 3525,319 J4.1
3V3bd: C1.2 C7.1 C33.2 J1.3 J3.1 Reg3.3 RRst.2 U1.1 U1.2 U1.7 UC1.18 | length 6509.2
  Top Layer w15: U1.7 1731.02,2809.02 1739.05,2801 ; U1.2 1864.9,2946 1913.51,2946 v1(1939,2920.51)
  Top Layer w20: RRst.2 UC1.18@852.56,1711.34
  Top Layer w35: UC1.18@850.1,1724 1138,1724 1138,1833 1170,1865 1170,2710 1261,2801 1739.05,2801 1871,2801 v1(1873,2799) ; J1.3@1002,847 J1.3 1005,1015 1205,1215 J3.1 1205,1662 1134,1733 ; v1(3364,755) C7.1 Reg3.3
  Bottom Layer w35: J1.3 1005,649 3258,649 v1(3364,755) ; v1(1873,2799) 1939,2865 v1(1939,2920.51)
5V: C2.2 C5.2 C8.1 C9.2 C51.2 IOP_1.1 IOP_1.2 IOP_1.3 IOP_1.4 IOP_1.5 IOP_1.6 IOP_1.7 IOP_1.8 IOP_2.1 IOP_2.2 IOP_2.3 IOP_2.4 IOP_2.5 IOP_2.6 IOP_2.7 IOP_2.8 J4.2 J4.4 Reg3.1 Reg5.2 Reg5.4 Rst1.2 UC2.3 UI1.9 | length 8015.8
  Top Layer w20: UC2.3 C51.2 1027.44,2984.44 v1(1103,3060) ; v1(1105,3421) 1111,3415 UI1.9 ; v1(1904,3370) 1905.56,3371.56 Rst1.2 ; J4.4 J4.2 3525,49 3895,49 3915,69 3915,1106 v1(3913,1106) ; C9.2 3563.45,1107 Reg3.1 3650.45,1107.55 v1(3652,1106)
  Top Layer w35: 2479,892 Reg5.4 ; 2709.71,609.29 Reg5.4 ; 2709.71,1188.29 Reg5.4 ; Reg5.2 Reg5.4
  Bottom Layer w20: v1(1103,3060) 1103,3419 v1(1105,3421) 1105,3590.94 1055.47,3640.47 1055.47,3727.81 1067.19,3739.53 1105,3739.53 IOP_2.1 ; 1570,3790 1590,3770 v1(1590,3444) 1664,3370 v1(1904,3370) ; v1(3652,1106) v1(3913,1106)
  Bottom Layer w80: IOP_2.8 IOP_2.7 IOP_2.6 IOP_2.5 IOP_2.4 IOP_2.3 IOP_2.2 IOP_2.1 1570,3790 IOP_1.8 IOP_1.7 IOP_1.6 IOP_1.5 IOP_1.4 IOP_1.3 IOP_1.2 IOP_1.1
12V: C3.2 C4.2 DI1.2 DI2.2 PWRP+.1 Reg5.3 RL1.2 RL2.2 RLY1_+.1 RLY2_+.1 U1.16 | length 1669.9
  Top Layer w10: U1.16 1890,2694.49 1890,2680 1894,2676 1904,2676
  Top Layer w20: 1904,2676 1908.08,2671.92 1908.08,2602.92 1909.5,2601.5
  Top Layer w25: 1909.5,2601.5 v1@1964,2547
  Top Layer w30: DI2.2 2504.76,3150.24 RLY2_+.1 ; Reg5.3 3193,992 3215.6,1014.6 C4.2 3221.6,1099 C3.2
  Top Layer w35: RL1.2 2195,2539 2203.76,2530.24 DI1.2 ; RL2.2 2195,3180 2224.76,3150.24 DI2.2
  Bottom Layer w30: DI1.2 2363.24,2502 RLY1_+.1
  Bottom Layer w35: v1(1963,2546) ccw(c2001.06,2584.06) 2001.06,2530.24 DI1.2
AUX_CL: J2.1
AUX_DA: J2.3
C\S\: J3.3 J4.24 | length 2738.6
  Top Layer w15: v1(956,373) 2359,373 v1(2377,355)
  Bottom Layer w15: v1(956,373) 957.97,374.97 957.97,1402.97 J3.3 ; v1(2377,355) 2377,208 2420,165 J4.24
CAN_RXD: R1.2 R2.2 UC1.2 | length 268.9
  Top Layer w10: UC1.2 R2.2 R1.2
CAN_TXD: UC1.1 UC2.1 | length 579.6
  Top Layer w15: UC1.1@843.03,2083.07 UC1.1 845,2440 924.49,2519.49 UC2.1
CANH: DioCAN1.1 P1.1 RCH1.2 RTERM1.2 UC2.7 | length 671.8
  Top Layer w10: P1.1 189,2643 207.44,2661.44 272.99,2661.44 296.43,2638 455.77,2638 DioCAN1.1 459.33,2641.56 RCH1.2 ; RCH1.2@550,2637.56 556.81,2644.37 624.37,2644.37 655,2675 UC2.7
CANL: DioCAN1.2 P1.2 RCL1.2 RTERM1.1 UC2.6 | length 652.2
  Top Layer w10: P1.2 192,2743 218.44,2716.56 294.99,2716.56 297.43,2719 454.77,2719 DioCAN1.2 460.41,2717.44 RCL1.2 RCL1.2 624.37,2717.4 ; 624.21,2717.56 624.37,2717.4 ; UC2.6 660,2725 652.4,2717.4 624.37,2717.4
FSYNC: J2.2
GND: C1.1 C2.1 C3.1 C4.1 C5.1 C6.1 C7.2 C8.2 C9.1 C33.1 C51.1 CH1.2 CL1.1 CO1.1 CO2.2 Crst1.1 DioCAN1.3 IOG_1.1 IOG_1.2 IOG_1.3 IOG_1.4 IOG_1.5 IOG_1.6 IOG_1.7 IOG_1.8 IOG_2.1 IOG_2.2 IOG_2.3 IOG_2.4 IOG_2.5 IOG_2.6 IOG_2.7 IOG_2.8 J1.4 J3.2 J4.6 J4.9 J4.14 J4.20 J4.25 J4.30 J4.34 J4.39 PWRN-.1 Q1.1 Q1.3 R2.1 RCAN1.1 Reg3.2 Reg3.4 Reg5.1 U1.8 U1.9 U1.15 UC1.9 UC2.2 UI1.10 UI1.15 UI1.16 UI1.17 X1.2 X1.4 | length 2841
  Top Layer w10: 1838,2630 1860,2652 U1.15@1860,2675
  Top Layer w15: v1(313,2678) DioCAN1.3 ; v1(1976,3000) 1988.5,2987.5 Q1.3
  Top Layer w30: C4.1 3296.4,1099 C4.1@3296.4,1107 ; C3.1 C4.1@3296.4,1107 ; Reg3.4 Reg3.2 3397,1017 3385.44,1028.56 C9.1 C4.1@3296.4,1107
  Top Layer w60: Reg5.1@3123.09,775 3123.09,664.91 3168,620 3663,620 3689.99,646.99 C7.2 3752,755 3814,817 Reg3.4 3814,1268
  Top Layer w70: C8.2 2366,1418 2398,1450 PWRN-.1
  Bottom Layer w70: 2536,1376 2536,1595
  other v1: 3797,792 3813,886 3814,1147 3812,1247
GPIO2: J1.2 J4.3 | length 3244.1
  Top Layer w15: v1(1105,526) J1.2 ; v1(1114,62) 1119.48,56.52 3302.52,56.52 3372.03,126.03 3372.03,216.03 3421,265 J4.3
  Bottom Layer w15: v1(1105,526) 1105,71 v1(1114,62)
GPIO3: J1.1 J4.5 | length 2607.2
  Top Layer w15: J1.1 1205,573 1223,555 2497,555 2614,438 3293,438 3325,406 J4.5
GPIO4: J4.7 UC1.16 UI1.11 | length 6076.9
  Top Layer w15: v1(753,1852) 745,1844 UC1.16 745,603 873.5,474.5 2447.5,474.5 2516.5,405.5 3205.5,405.5 3225,386 J4.7 ; v1(753,3308) 760,3315 UI1.11
  Bottom Layer w15: v1(753,1852) v1(753,3308)
GPIO7: J4.26
GPIO12: J4.32 UI1.20 | length 3821.8
  Top Layer w15: UI1.20 1885,3415 1903,3433 v1(2000,3433) ; v1(2063,596) 2063,661 1726,998 1726,1746 2063,2083 v1(2063,2677)
  Bottom Layer w15: v1(2000,3433) 2064,3369 v1@2064,2677 ; J4.32 2072.03,212.03 2072.03,296.51 2064,304.53 v1@2064,596
GPIO13: J4.33
GPIO14: J4.8
GPIO15: J4.10
GPIO16: J4.36 UI1.19 | length 3438.8
  Top Layer w15: v1(1598,2715) 1598,769 v1(1773,594) ; v1(1600,2890) 1600,3299 1666,3365 UI1.19
  Bottom Layer w15: v1(1598,2715) 1600,2717 v1(1600,2890) ; v1@1772.03,594 1772.03,217.97 J4.36
GPIO17: J4.11
GPIO18: J4.12
GPIO19: J4.35
GPIO20: J4.38 UC1.12 | length 2542.6
  Top Layer w15: UC1.12 545,558 767.39,335.61 1620.89,335.61 1677.97,278.53 1677.97,212.03 J4.38
GPIO22: J4.15
GPIO23: J4.16
GPIO24: J4.18
GPIO25: J4.22
GPIO26: J4.37
GPIO27: J4.13
ID_SC: J4.28
ID_SD: J4.27
INT: J3.4
IOA_0: IOS1.1 UI1.21 | length 1041.8
  Top Layer w15: UI1.21 1809.73,3465 1834.73,3490 v1(1898,3490)
  Bottom Layer w15: v1(1898,3490) 1982,3490 2083,3591 2650,3591 2705,3646 IOS1.1
IOA_1: IOS1.2 UI1.22 | length 901.5
  Top Layer w15: UI1.22 1877.04,3515 1884.54,3522.5 1911.46,3522.5 1918.96,3515 2208,3515 2231,3538 2453,3538 IOS1.2
IOA_2: IOS1.3 UI1.23 | length 796.6
  Top Layer w15: UI1.23 1812.06,3565 1834.09,3542.97 1869.66,3542.97 1874.18,3547.5 1921.82,3547.5 1926.34,3542.97 2198.33,3542.97 2227.36,3572 2387,3572 IOS1.3
IOA_3: IOS1.4 UI1.24 | length 696.6
  Top Layer w15: UI1.24 1809.73,3615 1856.75,3567.97 1859.3,3567.97 1863.83,3572.5 1932.17,3572.5 1936.7,3567.97 2187.97,3567.97 2227,3607 2322,3607 IOS1.4
IOA_4: IOS1.5 UI1.25 | length 592.9
  Top Layer w15: UI1.25 1809.73,3665 1877.23,3597.5 1942.53,3597.5 1947.06,3592.97 2164,3592.97 2203.03,3632 2247,3632 IOS1.5
IOA_5: IOS1.6 UI1.26 | length 492.9
  Top Layer w15: UI1.26 1809.73,3715 1902.23,3622.5 1952.88,3622.5 1957.41,3617.97 2132.97,3617.97 IOS1.6
IOA_6: IOS1.7 UI1.27 | length 392.9
  Top Layer w15: UI1.27 1809.73,3765 1927.23,3647.5 1963.24,3647.5 1967.77,3642.97 2057.97,3642.97 IOS1.7
IOA_7: IOS1.8 UI1.28 | length 274.6
  Top Layer w15: UI1.28 1824,3815 1949,3690 IOS1.8
IOB_0: IOS2.1 UI1.1 | length 374.6
  Top Layer w15: IOS2.1 1230,3815 UI1.1
IOB_1: IOS2.2 UI1.2 | length 492.9
  Top Layer w15: IOS2.2 1052.03,3642.97 1163.51,3642.97 1285.54,3765 UI1.2
IOB_2: IOS2.3 UI1.3 | length 592.9
  Top Layer w15: IOS2.3 977.03,3617.97 1173.87,3617.97 1270.9,3715 UI1.3
IOB_3: IOS2.4 UI1.4 | length 692.9
  Top Layer w15: IOS2.4 902.03,3592.97 1184.22,3592.97 1256.25,3665 UI1.4
IOB_4: IOS2.5 UI1.5 | length 792.9
  Top Layer w15: IOS2.5 827.03,3567.97 1194.58,3567.97 1241.61,3615 UI1.5
IOB_5: IOS2.6 UI1.6 | length 892.9
  Top Layer w15: IOS2.6 752.03,3542.97 1204.93,3542.97 1226.96,3565 UI1.6
IOB_6: IOS2.7 UI1.7 | length 995.3
  Top Layer w15: IOS2.7 680,3515 UI1.7
IOB_7: IOS2.8 UI1.8 | length 1116
  Top Layer w15: IOS2.8 630,3465 UI1.8
NetCH1_1: CH1.1 RCH1.1 | length 60.3
  Top Layer w20: RCH1.1 553,2527.56 CH1.1
NetCL1_2: CL1.2 RCL1.1 | length 69.9
  Top Layer w20: RCL1.1 CL1.2
NetCO1_2: CO1.2 UC1.7 X1.3 | length 279.4
  Top Layer w15: X1.3 528.5,2321.5 547.44,2302.56 CO1.2 545,2187.56 UC1.7
NetCO2_1: CO2.1 UC1.8 X1.1 | length 242.6
  Top Layer w15: X1.1 411.69,2190.87 CO2.1 422.56,2180 475,2180 495,2160 UC1.8
NetCrst1_2: Crst1.2 Rst1.1 UI1.18 | length 200.4
  Top Layer w10: UI1.18 1980.56,3315 Rst1.1
NetD1_1: D1.1 DI1.1 Q1.5 Q1.6 RLY1_Rtn.1 | length 577.6
  Top Layer w35: 2095,2972 2095,2852 2135.5,2811.5 D1.1 2333.27,2811.5 DI1.1 2534.76,2809.76 RLY1_Rtn.1
NetD1_2: D1.2 RL1.1 | length 95
  Top Layer w20: RL1.1 D1.2
NetD2_1: D2.1 DI2.1 Q1.7 Q1.8 RLY2_Rtn.1 | length 825.9
  Top Layer w35: 2094,3024 2094,3394 2121.5,3421.5 D2.1 2203.27,3429.76 DI2.1 2534.76,3429.76 RLY2_Rtn.1
NetD2_2: D2.2 RL2.1 | length 75
  Top Layer w20: RL2.1 D2.2
NetQ1_2: Q1.2 U1.5 | length 376.9
  Top Layer w15: U1.5 1783.56,2941.44 1783.56,3026.92 1806.64,3050 1983.8,3050 2021.3,3012.5 Q1.2
NetQ1_4: Q1.4 U1.4 | length 363.2
  Top Layer w15: U1.4@1808.56,2931.08 1808.56,3016.56 1817,3025 1891,3025 1964.22,2951.78 2011.59,2951.78 2022.3,2962.5 Q1.4
NetR1_1: R1.1 UC2.4 | length 536.3
  Top Layer w10: R1.1 739.88,2394.88 790,2445 790,2606.26 803.82,2620.08 803.82,2713.82 865,2775 UC2.4
NetRCAN1_2: RCAN1.2 UC2.8 | length 67.7
  Top Layer w15: RCAN1.2 735.51,2558.07 UC2.8
NetRRst_1: RRst.1 UC1.17 | length 136.5
  Top Layer w15: RRst.1@795,1582.44 UC1.17
RELAY1: J4.29 U1.3 | length 3164.1
  Top Layer w15: U1.3@1833.56,2940.08 1833.56,2888.44 1848,2874 1932.36,2874 2141.91,2664.45 2141.91,2038.91 1793,1690 1793,1011.91 2141.91,663 2141.91,604.09 v1(2152,594)
  Bottom Layer w15: J4.29 2116,274 2152,310 v1(2152,594)
RELAY2: J4.31 U1.6 | length 3153.5
  Top Layer w15: U1.6 1756.61,2877.39 1795,2839 1932,2839 2005.5,2765.5 2005.5,2120.5 1659,1774 1659,926 v1(1989,596)
  Bottom Layer w15: v1(1989,596) 1989,301 J4.31
SPI_MISO: J4.21 UI1.14 | length 4434.3
  Top Layer w15: v1(1300,3145) 1320,3165 UI1.14 ; v1(1303,2728) 1301.12,2726.12 1301.12,2311.12 1249,2259 1249,1989.12 1301.12,1937 1301.12,1076.12 1156,931 1156,553 1189,520 2455,520 v1(2531,444)
  Bottom Layer w15: v1(1300,3145) 1301.12,3143.88 v1@1301.12,2728 ; J4.21 2525,438 v1(2531,444)
SPI_MOSI: J4.19 UC1.14 | length 3294
  Top Layer w15: UC1.14 645,613 810,448 2416,448 2496,368 v1(2626,368)
  Bottom Layer w15: J4.19 2627,267 v1@2627,367 ; v1(2626,368) v1@2627,367 ; v1@2628,366 v1@2627,367
SPI_MOSIA: UC1.15 UI1.13 | length 2255.3
  Top Layer w15: UC1.15@695,1680.19 UC1.15 v1(695,1875) ; v1(712,3211) 1376.96,3211 1380.96,3215 UI1.13
  Bottom Layer w15: v1(695,1875) 712,1892 v1(712,3211)
SPI_SCLK: J4.23 UC1.13 UI1.12 | length 5548.4
  Top Layer w15: v1(595,1834) UC1.13 595,580 769.5,405.5 2403.5,405.5 v1(2429,380) ; v1(599,3260) 792,3260 793,3261 1376.96,3261 1380.96,3265 UI1.12
  Bottom Layer w15: v1(595,1834) 595,3260 v1(599,3260) ; J4.23 2429,269 v1(2429,380)
pads on no net: J4.40 PWRN-.MH PWRP+.MH RLY1_+.MH RLY1_Rtn.MH RLY2_+.MH RLY2_Rtn.MH U1.10 U1.11 U1.12 U1.13 U1.14 UC1.3 UC1.4 UC1.5 UC1.6 UC1.10 UC1.11 UC2.5
copper on no net:
  other v2: 1440.67,196.07 3724.13,196.07 1440.67,2125.2 3724.13,2125.2

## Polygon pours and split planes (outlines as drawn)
no net on GND (split plane): 3984.9,20.1 20.1,20.1 20.1,3979.9 3984.9,3979.9
no net on 5V (split plane): 3984.9,20.1 20.1,20.1 20.1,3979.9 3984.9,3979.9

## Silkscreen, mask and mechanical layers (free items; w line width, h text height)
Top Overlay:
  text "+12V  RTN RLY2" at 3985,3020 h60 r90
  text "RLY1  +12V  RTN" at 3985,2080 h60 r90
Board Outline:
  the board outline again, w3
